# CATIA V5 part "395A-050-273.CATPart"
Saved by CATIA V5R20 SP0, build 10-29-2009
Part number: 395A-050-273
Source: Unknown
Property "ARTICLENO": "395A-050-273"
Property "B": "10"
Property "BOMINFO": "395A-050-273"
Property "C": "16.000"
Property "CODE": "395A-050-273"
Property "D": "50.000"
Property "D1": "60.000"
Property "D2": "4x15"
Property "D3": "24"
Property "D5": "38"
Property "D6": "36.000"
Property "H": "6.000"
Property "L": "273.000"
Property "L1": "11.000"
Property "L2": "230.000"
Property "L3": "15.000"
Property "L4": "16"
Property "LINA": "395A-050-273"
Property "M": "20.000"
Property "M1": "16.000"
Property "M2": "16.000"
Property "MAXLOAD": "8000 Kg"
Property "MDW": "16000 Kg"
Property "NB": "395A-050-273"
Property "NBSYN": "$CODE."
Property "NN": "395A"
Property "NT": "Pin"
Property "P": "7"
Property "S": "15.000"
Property "SUPPLIER": "CF"
Bounding box of the stored display mesh (mm): x 0 to 273, y -31 to 30, z -30 to 30
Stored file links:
  C:\Users\Utente\Desktop\3D files 395A\395A-050-273.CATPart
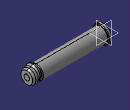
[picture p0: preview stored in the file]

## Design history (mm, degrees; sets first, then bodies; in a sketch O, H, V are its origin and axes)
Body1 "Geometry.1" (main body)
  Solid1 "395A-050-273.catpart": solid without history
